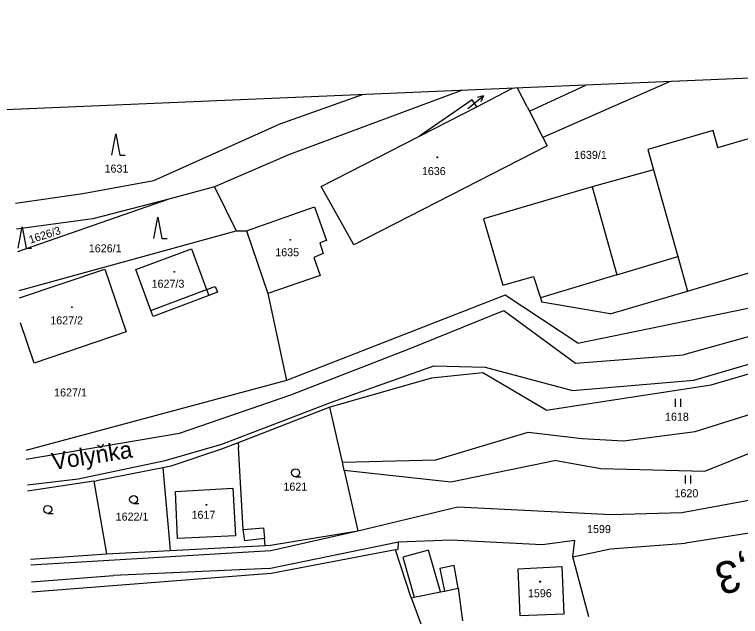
# Model space of a CAD drawing. Extents: x -806456 to -805395, y -1150847 to -1150506.
# Drawn here: x -806245.9 to -806109.9, y -1150636.7 to -1150523.9 of the extents above; entities that cross this region are included whole.
import ezdxf

# ---------------------------------------------------------------- set-up
doc = ezdxf.new("R2010")
doc.units = 0
for name, color, linetype in [('Default', 7, 'Continuous'), ('formát', 7, 'Continuous'), ('kilometráž - vrstava 7', 7, 'Continuous'), ('kn_celek - Cisla parcel pomocna', 7, 'Continuous'), ('kn_celek - Cisla pozemkovych parcel', 7, 'Continuous'), ('kn_celek - Cisla stavebnich parcel', 7, 'Continuous'), ('kn_celek - Dalsi prvky mapy popis', 7, 'Continuous'), ('kn_celek - Hranice parcel', 7, 'Continuous'), ('kn_celek - Vnitrni kresby', 7, 'Continuous'), ('kn_celek - Znacky budov', 7, 'Continuous'), ('kn_celek - Znacky kultur', 7, 'Continuous')]:
    doc.layers.add(name, color=color, linetype=linetype)

# ---------------------------------------------------------------- blocks, each defined once
blk = doc.blocks.new('306')
at = {"layer": 'Default'}
for p, q in [((-5.2, 0), (-5.2, 15)), ((4.8, 0), (4.8, 15))]:
    blk.add_line(p, q, dxfattribs=at)
blk = doc.blocks.new('304')
at = {"layer": 'Default'}
blk.add_line((-0.1, 0), (9.9, 0), dxfattribs=at)
blk.add_circle((-0.1, 7.5), 7.5, dxfattribs=at)
blk = doc.blocks.new('308')
at = {"layer": 'Default'}
for p, q in [((-7.5, 0.2), (0, 40.2)), ((0, 40.2), (7.5, 0.2)), ((7.5, 0.2), (17.5, 0.2))]:
    blk.add_line(p, q, dxfattribs=at)
blk = doc.blocks.new('402')
at = {"layer": 'Default'}
for p, q in [((-0.8, 0.8), (0.7, 0.8)), ((-0.8, 0.8), (-0.8, -0.7)), ((0.7, 0.8), (0.7, -0.7)), ((0.7, -0.7), (-0.8, -0.7))]:
    blk.add_line(p, q, dxfattribs=at)
blk = doc.blocks.new('Z61')
at = {"layer": 'Default'}
for p, q in [((0, 0), (30, 0)), ((30, 0), (19.2, 5.3)), ((30, 0), (19.2, -5.3))]:
    blk.add_line(p, q, dxfattribs=at)

msp = doc.modelspace()

# ---------------------------------------------------------------- linework, layer by layer
at = {"layer": 'formát'}
msp.add_line((-805826.83, -1150523.88), (-806456.26, -1150550.6), dxfattribs=at)
at = {"layer": 'kn_celek - Cisla parcel pomocna'}
msp.add_line((-806160.93, -1150541.48), (-806160.36, -1150541.02), dxfattribs=at)
at = {"layer": 'kn_celek - Hranice parcel'}
for p, q in [((-806123.07, -1150536.45), (-806146.9, -1150546.91)), ((-806162.14, -1150538.11), (-806194.35, -1150550.11)), ((-806159.28, -1150541.15), (-806152.59, -1150537.71)), ((-806149.84, -1150541.15), (-806151.64, -1150537.66)), ((-806149.42, -1150541.98), (-806138.84, -1150537.12)), ((-806180.55, -1150538.89), (-806196.55, -1150544.56)), ((-806160.15, -1150539.84), (-806170.03, -1150546.67)), ((-806159.28, -1150541.15), (-806160.15, -1150539.84)), ((-806170.03, -1150546.67), (-806159.28, -1150541.15)), ((-806149.84, -1150541.15), (-806149.42, -1150541.98)), ((-806219.77, -1150554.97), (-806196.55, -1150544.56)), ((-806114.14, -1150548.78), (-806100.8, -1150544.86)), ((-806115.04, -1150545.59), (-806127.23, -1150549.2)), ((-806114.14, -1150548.78), (-806115.04, -1150545.59)), ((-806188.43, -1150556.12), (-806170.03, -1150546.67)), ((-806146.9, -1150546.91), (-806146.09, -1150548.48)), ((-806146.09, -1150548.48), (-806182.32, -1150567.05)), ((-806127.23, -1150549.2), (-806126.18, -1150552.98)), ((-806194.35, -1150550.11), (-806208.43, -1150556.15)), ((-806126.18, -1150552.98), (-806137.69, -1150556.16)), ((-806233.07, -1150557.4), (-806219.77, -1150554.97)), ((-806245.71, -1150559.22), (-806233.07, -1150557.4)), ((-806208.43, -1150556.15), (-806216.94, -1150558.47)), ((-806208.43, -1150556.15), (-806204.38, -1150564.44)), ((-806182.32, -1150567.05), (-806188.43, -1150556.12)), ((-806137.69, -1150556.16), (-806158, -1150562.17)), ((-806216.94, -1150558.47), (-806245.32, -1150568.33)), ((-806216.94, -1150558.47), (-806231.19, -1150562.18)), ((-806202.43, -1150564.42), (-806189.65, -1150559.95)), ((-806189.65, -1150559.95), (-806187.41, -1150566.26)), ((-806231.19, -1150562.18), (-806245.5, -1150564.13)), ((-806158, -1150562.17), (-806154.41, -1150574.62)), ((-806245.01, -1150575.6), (-806204.38, -1150564.44)), ((-806204.38, -1150564.44), (-806202.43, -1150564.42)), ((-806202.43, -1150564.42), (-806198.39, -1150576.16)), ((-806187.41, -1150566.26), (-806188.71, -1150566.65)), ((-806188.71, -1150566.65), (-806188.04, -1150568.69)), ((-806223.16, -1150571.68), (-806212.71, -1150567.8)), ((-806212.71, -1150567.8), (-806209.9, -1150575.43)), ((-806188.04, -1150568.69), (-806189.82, -1150569.39)), ((-806189.82, -1150569.39), (-806188.62, -1150572.79)), ((-806244.95, -1150576.99), (-806228.93, -1150571.58)), ((-806228.93, -1150571.58), (-806224.97, -1150583.34)), ((-806220.34, -1150579.33), (-806223.16, -1150571.68)), ((-806119.82, -1150575.72), (-806104.61, -1150571.2)), ((-806188.62, -1150572.79), (-806198.39, -1150576.16)), ((-806154.41, -1150574.62), (-806148.65, -1150572.95)), ((-806148.65, -1150572.95), (-806147.32, -1150577)), ((-806140.34, -1150585.49), (-806082.33, -1150573.48)), ((-806209.9, -1150575.43), (-806208.26, -1150574.82)), ((-806208.26, -1150574.82), (-806207.84, -1150575.94)), ((-806207.84, -1150575.94), (-806209.48, -1150576.55)), ((-806198.39, -1150576.16), (-806194.91, -1150592.47)), ((-806134.33, -1150579.95), (-806119.82, -1150575.72)), ((-806209.48, -1150576.55), (-806219.91, -1150580.45)), ((-806153.97, -1150576.46), (-806194.91, -1150592.47)), ((-806140.34, -1150585.49), (-806153.97, -1150576.46)), ((-806147.32, -1150577), (-806147.11, -1150577.79)), ((-806134.33, -1150579.95), (-806147.11, -1150577.79)), ((-806115.37, -1150593.3), (-806058.91, -1150576.7)), ((-806219.91, -1150580.45), (-806220.34, -1150579.33)), ((-806242.2, -1150589.19), (-806244.75, -1150581.67)), ((-806224.97, -1150583.34), (-806242.2, -1150589.19)), ((-806158.16, -1150591.06), (-806167.78, -1150592.03)), ((-806146.31, -1150598.02), (-806158.16, -1150591.06)), ((-806194.91, -1150592.47), (-806243.74, -1150605.6)), ((-806167.78, -1150592.03), (-806186.81, -1150597.44)), ((-806146.31, -1150598.02), (-806115.37, -1150593.3)), ((-806118.38, -1150602.03), (-806101.77, -1150596.83)), ((-806116.57, -1150609.49), (-806083.6, -1150596.08)), ((-806186.81, -1150597.44), (-806203.96, -1150604.13)), ((-806184.46, -1150607.76), (-806186.81, -1150597.44)), ((-806166.93, -1150607.33), (-806149.67, -1150602.17)), ((-806149.67, -1150602.17), (-806139.52, -1150603.34)), ((-806131.79, -1150603.78), (-806118.38, -1150602.03)), ((-806139.52, -1150603.34), (-806131.79, -1150603.78)), ((-806203.96, -1150604.13), (-806207.3, -1150605.43)), ((-806203.96, -1150604.13), (-806203.91, -1150605.03)), ((-806207.3, -1150605.43), (-806216.59, -1150608.54)), ((-806203.07, -1150620.38), (-806203.91, -1150605.03)), ((-806184.46, -1150607.76), (-806166.93, -1150607.33)), ((-806144.39, -1150607.43), (-806164.16, -1150611.54)), ((-806144.39, -1150607.43), (-806136.05, -1150608.98)), ((-806218.07, -1150608.83), (-806230.48, -1150611.28)), ((-806216.59, -1150608.54), (-806218.07, -1150608.83)), ((-806218.07, -1150608.83), (-806216.9, -1150622.15)), ((-806184.11, -1150609.31), (-806184.46, -1150607.76)), ((-806136.05, -1150608.98), (-806116.57, -1150609.49)), ((-806184.11, -1150609.31), (-806181.54, -1150620.62)), ((-806164.16, -1150611.54), (-806184.11, -1150609.31)), ((-806231.04, -1150611.36), (-806243.41, -1150613.21)), ((-806231.04, -1150611.36), (-806230.48, -1150611.28)), ((-806231.04, -1150611.36), (-806228.66, -1150624.97)), ((-806120.89, -1150617.2), (-806095.36, -1150612.49)), ((-806181.54, -1150620.62), (-806162.83, -1150616.14)), ((-806162.83, -1150616.14), (-806134.13, -1150617.55)), ((-806134.13, -1150617.55), (-806120.89, -1150617.2)), ((-806094.01, -1150618.9), (-806120.22, -1150622.93)), ((-806203.07, -1150620.38), (-806199.26, -1150620.1)), ((-806199.26, -1150620.1), (-806199.07, -1150622.09)), ((-806197.89, -1150623.33), (-806181.54, -1150620.62)), ((-806216.9, -1150622.15), (-806216.71, -1150624.33)), ((-806198.95, -1150623.39), (-806199.07, -1150622.09)), ((-806173.92, -1150622.7), (-806164.16, -1150622.33)), ((-806164.16, -1150622.33), (-806147.06, -1150623.22)), ((-806147.06, -1150623.22), (-806140.94, -1150622.38)), ((-806141.27, -1150625.54), (-806140.94, -1150622.38)), ((-806216.71, -1150624.33), (-806198.95, -1150623.39)), ((-806198.95, -1150623.39), (-806197.89, -1150623.33)), ((-806174.02, -1150624.06), (-806173.92, -1150622.7)), ((-806141.27, -1150625.54), (-806134.21, -1150624)), ((-806134.21, -1150624), (-806120.22, -1150622.93)), ((-806242.87, -1150625.98), (-806228.66, -1150624.97)), ((-806228.66, -1150624.97), (-806216.71, -1150624.33)), ((-806174.5, -1150624.21), (-806197.79, -1150628.63)), ((-806174.5, -1150624.21), (-806174.02, -1150624.06)), ((-806171.55, -1150633.2), (-806174.5, -1150624.21)), ((-806138.31, -1150636.79), (-806141.27, -1150625.54)), ((-806208.27, -1150629.45), (-806242.61, -1150632.14)), ((-806197.79, -1150628.63), (-806208.27, -1150629.45)), ((-806171, -1150633.09), (-806166.1, -1150632.08)), ((-806166.1, -1150632.08), (-806165.36, -1150631.93)), ((-806165.36, -1150631.93), (-806162.76, -1150631.39)), ((-806162.76, -1150631.39), (-806161.95, -1150637.48)), ((-806171.55, -1150633.2), (-806171, -1150633.09)), ((-806171.55, -1150633.2), (-806171.35, -1150633.83)), ((-806171.35, -1150633.83), (-806164.09, -1150653.24))]:
    msp.add_line(p, q, dxfattribs=at)
at = {"layer": 'kn_celek - Vnitrni kresby'}
for p, q in [((-806149.42, -1150541.98), (-806146.9, -1150546.91)), ((-806126.18, -1150552.98), (-806121.64, -1150569.21)), ((-806137.69, -1150556.16), (-806133.04, -1150572.67)), ((-806133.04, -1150572.67), (-806121.64, -1150569.21)), ((-806121.64, -1150569.21), (-806119.82, -1150575.72)), ((-806060.49, -1150570.78), (-806120.54, -1150587.67)), ((-806133.04, -1150572.67), (-806147.32, -1150577)), ((-806220.34, -1150579.33), (-806209.9, -1150575.43)), ((-806209.9, -1150575.43), (-806209.48, -1150576.55)), ((-806171.95, -1150586.52), (-806154.24, -1150579.33)), ((-806154.24, -1150579.33), (-806140.77, -1150589.25)), ((-806118.66, -1150592.4), (-806082.8, -1150581.88)), ((-806194.14, -1150595.16), (-806171.95, -1150586.52)), ((-806140.77, -1150589.25), (-806120.54, -1150587.67)), ((-806186.48, -1150596.5), (-806167.32, -1150589.72)), ((-806167.32, -1150589.72), (-806157.73, -1150589.99)), ((-806157.73, -1150589.99), (-806141.34, -1150594.32)), ((-806141.34, -1150594.32), (-806118.66, -1150592.4)), ((-806214.96, -1150602.32), (-806194.14, -1150595.16)), ((-806207.02, -1150604.43), (-806186.48, -1150596.5)), ((-806243.67, -1150607.22), (-806214.96, -1150602.32)), ((-806217.64, -1150607.46), (-806207.02, -1150604.43)), ((-806233.94, -1150610.9), (-806217.64, -1150607.46)), ((-806243.46, -1150612.02), (-806233.94, -1150610.9)), ((-806215.7, -1150613.3), (-806204.99, -1150612.67)), ((-806204.99, -1150612.67), (-806204.45, -1150621.61)), ((-806215.36, -1150622.08), (-806215.7, -1150613.3)), ((-806202.73, -1150622.52), (-806203.07, -1150620.38)), ((-806197.87, -1150624.33), (-806181.54, -1150620.62)), ((-806204.45, -1150621.61), (-806215.36, -1150622.08)), ((-806199.07, -1150622.09), (-806202.73, -1150622.52)), ((-806198.21, -1150627.73), (-806173.92, -1150622.7)), ((-806242.83, -1150627.04), (-806197.87, -1150624.33)), ((-806168.3, -1150624.24), (-806173.13, -1150625.56)), ((-806166.1, -1150632.08), (-806168.3, -1150624.24)), ((-806173.13, -1150625.56), (-806171, -1150633.09)), ((-806198.21, -1150627.73), (-806227.3, -1150629)), ((-806163.53, -1150627.15), (-806166.23, -1150627.67)), ((-806166.23, -1150627.67), (-806165.36, -1150631.93)), ((-806162.76, -1150631.39), (-806163.53, -1150627.15)), ((-806151.54, -1150627.79), (-806143.38, -1150627.34)), ((-806151.16, -1150636.6), (-806151.54, -1150627.79)), ((-806143.38, -1150627.34), (-806142.98, -1150636.24)), ((-806242.69, -1150630.23), (-806227.3, -1150629)), ((-806142.98, -1150636.24), (-806151.16, -1150636.6))]:
    msp.add_line(p, q, dxfattribs=at)

# ---------------------------------------------------------------- block references
at = {"layer": 'kn_celek - Cisla parcel pomocna', "xscale": 0.1, "yscale": 0.09999999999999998, "rotation": 38.80350000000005}
msp.add_blockref('Z61', (-806160.36, -1150541.02), dxfattribs=at)
at = {"layer": 'kn_celek - Znacky budov', "xscale": 0.1, "yscale": 0.10000000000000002}
for p in [(-806166.71, -1150550.64), (-806194.22, -1150566.1), (-806215.96, -1150572.09), (-806235.11, -1150578.73), (-806209.94, -1150615.79), (-806147.45, -1150630.18)]:
    msp.add_blockref('402', p, dxfattribs=at)
at = {"layer": 'kn_celek - Znacky kultur', "xscale": 0.1, "yscale": 0.10000000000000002}
for name, p in [('308', (-806226.87, -1150550.26)), ('308', (-806219.03, -1150565.87)), ('308', (-806244.42, -1150567.66)), ('306', (-806121.56, -1150597.41)), ('304', (-806193.22, -1150610.51)), ('306', (-806119.65, -1150611.75)), ('304', (-806223.55, -1150615.52)), ('304', (-806239.64, -1150617.39))]:
    msp.add_blockref(name, p, dxfattribs=at)

# ---------------------------------------------------------------- texts
at = {"layer": 'kilometráž - vrstava 7'}
msp.add_text('35,3', height=6, rotation=194.6315, dxfattribs=at).set_placement((-806100.01, -1150623))
at = {"layer": 'kn_celek - Cisla pozemkovych parcel'}
for s, height, p in [('1640', 0.1, (-806161.1, -1150541.45)), ('1639/1', 1.5, (-806141.07, -1150550.93)), ('1631', 1.5, (-806229, -1150553.5)), ('1626/1', 1.5, (-806231.95, -1150568.45)), ('1627/1', 1.5, (-806238.45, -1150595.46)), ('1618', 1.5, (-806124.03, -1150600.01)), ('1621', 1.5, (-806195.5, -1150613.11)), ('1620', 1.5, (-806122.25, -1150614.35)), ('1622/1', 1.5, (-806226.92, -1150618.73)), ('1599', 1.5, (-806138.63, -1150621.06))]:
    msp.add_text(s, height=height, dxfattribs=at).set_placement(p)
msp.add_text('1626/3', height=1.5, rotation=17.7615, dxfattribs=at).set_placement((-806242.91, -1150566.84))
at = {"layer": 'kn_celek - Cisla stavebnich parcel'}
for s, p in [('1636', (-806169.57, -1150553.97)), ('1635', (-806197.03, -1150569.18)), ('1627/3', (-806220.19, -1150575.08)), ('1627/2', (-806239.17, -1150581.95)), ('1617', (-806212.71, -1150618.39)), ('1596', (-806149.71, -1150633.09))]:
    msp.add_text(s, height=1.5, dxfattribs=at).set_placement(p)
at = {"layer": 'kn_celek - Dalsi prvky mapy popis'}
msp.add_text('Volyňka', height=3.2, rotation=9.0104, dxfattribs=at).set_placement((-806238.65, -1150609.27))

doc.saveas('drawing.dxf')
